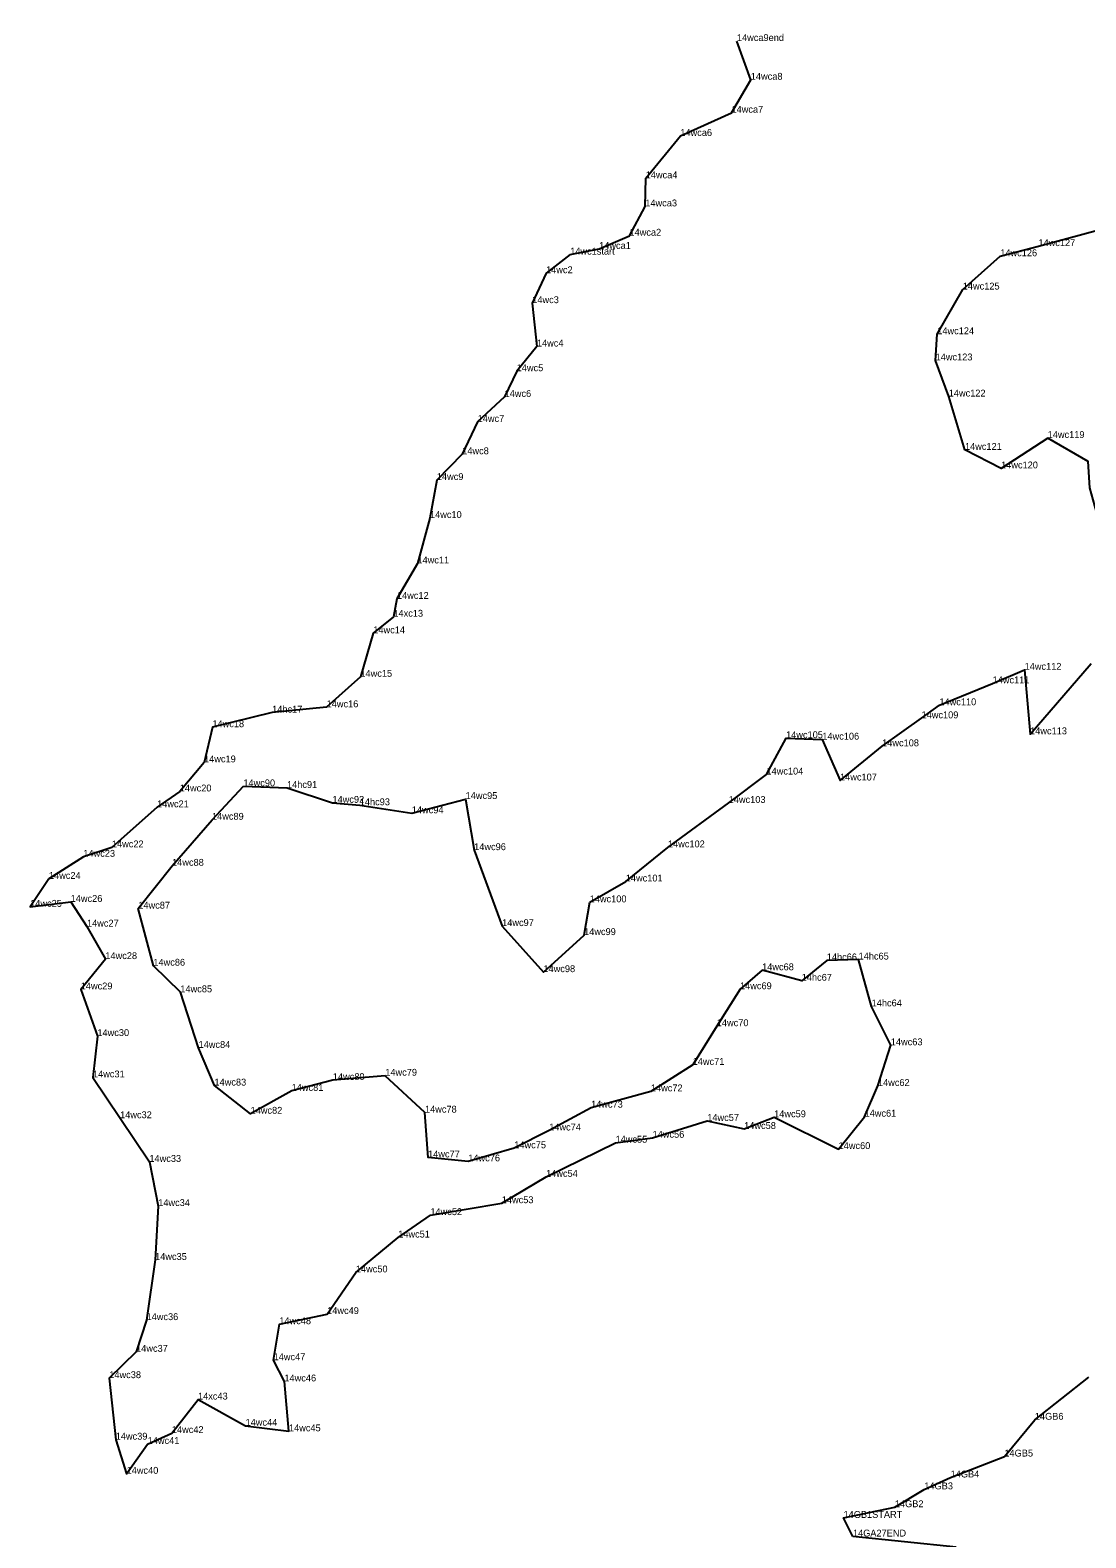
# Model space of a CAD drawing. Extents: x 2072529 to 2267990, y 436423 to 470008.
# Drawn here: x 2255744 to 2256512, y 441770 to 442866 of the extents above; entities that cross this region are included whole.
import ezdxf

# ---------------------------------------------------------------- set-up
doc = ezdxf.new("R2010")
doc.units = 0
doc.layers.add('Level 3', color=7, linetype='Continuous')
doc.layers.add('Old_Level_52', color=7, linetype='Continuous')

msp = doc.modelspace()

# ---------------------------------------------------------------- linework, layer by layer
at = {"layer": 'Level 3'}
for p, q in [((2256257.899, 442858.409), (2256257.899, 442858.409)), ((2256268.003, 442830.249), (2256268.003, 442830.249)), ((2256253.969, 442806.261), (2256253.969, 442806.261)), ((2256216.767, 442789.425), (2256216.767, 442789.425)), ((2256191.599, 442758.624), (2256191.599, 442758.624)), ((2256191.305, 442738.169), (2256191.305, 442738.169)), ((2256179.78, 442716.87), (2256179.78, 442716.87)), ((2256136.696, 442703.1), (2256136.696, 442703.1)), ((2256157.731, 442707.258), (2256157.731, 442707.258)), ((2256449.372, 442701.938), (2256449.372, 442701.938)), ((2256477.101, 442709.298), (2256477.101, 442709.298)), ((2256119.139, 442689.606), (2256119.139, 442689.606)), ((2256422.088, 442677.722), (2256422.088, 442677.722)), ((2256109.115, 442667.828), (2256109.115, 442667.828)), ((2256403.543, 442645.218), (2256403.543, 442645.218)), ((2256112.493, 442636.286), (2256112.493, 442636.286)), ((2256402.361, 442626.184), (2256402.361, 442626.184)), ((2256097.804, 442618.346), (2256097.804, 442618.346)), ((2256088.992, 442599.644), (2256088.992, 442599.644)), ((2256411.887, 442599.94), (2256411.887, 442599.94)), ((2256069.424, 442581.458), (2256069.424, 442581.458)), ((2256483.83, 442569.775), (2256483.83, 442569.775)), ((2256058.196, 442557.949), (2256058.196, 442557.949)), ((2256423.695, 442561.134), (2256423.695, 442561.134)), ((2256449.942, 442547.661), (2256449.942, 442547.661)), ((2256039.742, 442539.213), (2256039.742, 442539.213)), ((2256034.772, 442511.586), (2256034.772, 442511.586)), ((2256025.637, 442478.575), (2256025.637, 442478.575)), ((2256010.763, 442452.788), (2256010.763, 442452.788)), ((2256008.17, 442439.828), (2256008.17, 442439.828)), ((2255993.551, 442427.775), (2255993.551, 442427.775)), ((2255984.174, 442396.146), (2255984.174, 442396.146)), ((2256467.056, 442401.237), (2256467.056, 442401.237)), ((2256443.754, 442391.374), (2256443.754, 442391.374)), ((2255920.019, 442370.069), (2255920.019, 442370.069)), ((2255959.616, 442373.969), (2255959.616, 442373.969)), ((2256405.101, 442375.447), (2256405.101, 442375.447)), ((2255876.591, 442359.51), (2255876.591, 442359.51)), ((2256392.12, 442365.972), (2256392.12, 442365.972)), ((2256293.64, 442351.509), (2256293.64, 442351.509)), ((2256319.992, 442350.448), (2256319.992, 442350.448)), ((2256471.058, 442354.313), (2256471.058, 442354.313)), ((2256363.47, 442345.612), (2256363.47, 442345.612)), ((2255870.51, 442333.901), (2255870.51, 442333.901)), ((2255899.103, 442316.518), (2255899.103, 442316.518)), ((2255930.823, 442315.302), (2255930.823, 442315.302)), ((2256279.387, 442325.079), (2256279.387, 442325.079)), ((2256332.867, 442320.741), (2256332.867, 442320.741)), ((2255852.869, 442312.776), (2255852.869, 442312.776)), ((2255963.868, 442304.513), (2255963.868, 442304.513)), ((2256060.665, 442307.265), (2256060.665, 442307.265)), ((2256251.929, 442304.418), (2256251.929, 442304.418)), ((2255836.387, 442301.236), (2255836.387, 442301.236)), ((2255983.714, 442302.732), (2255983.714, 442302.732)), ((2256021.559, 442296.894), (2256021.559, 442296.894)), ((2255876.303, 442292.187), (2255876.303, 442292.187)), ((2255803.524, 442272.108), (2255803.524, 442272.108)), ((2256207.755, 442272.121), (2256207.755, 442272.121)), ((2255782.767, 442265.278), (2255782.767, 442265.278)), ((2256066.889, 442270.09), (2256066.889, 442270.09)), ((2255847.281, 442258.718), (2255847.281, 442258.718)), ((2255757.754, 442249.211), (2255757.754, 442249.211)), ((2256177.113, 442247.308), (2256177.113, 442247.308)), ((2255744.096, 442228.902), (2255744.096, 442228.902)), ((2255773.544, 442232.484), (2255773.544, 442232.484)), ((2255822.729, 442227.549), (2255822.729, 442227.549)), ((2256150.866, 442232.18), (2256150.866, 442232.18)), ((2255785.395, 442214.491), (2255785.395, 442214.491)), ((2256087.213, 442214.888), (2256087.213, 442214.888)), ((2256146.807, 442208.328), (2256146.807, 442208.328)), ((2255798.772, 442190.873), (2255798.772, 442190.873)), ((2255833.668, 442186.065), (2255833.668, 442186.065)), ((2256323.244, 442189.952), (2256323.244, 442189.952)), ((2256346.351, 442190.546), (2256346.351, 442190.546)), ((2256117.242, 442181.383), (2256117.242, 442181.383)), ((2256276.219, 442182.731), (2256276.219, 442182.731)), ((2256305.007, 442175.125), (2256305.007, 442175.125)), ((2255780.866, 442168.821), (2255780.866, 442168.821)), ((2255853.292, 442166.716), (2255853.292, 442166.716)), ((2256260.148, 442168.971), (2256260.148, 442168.971)), ((2256355.84, 442156.485), (2256355.84, 442156.485)), ((2256243.265, 442142.091), (2256243.265, 442142.091)), ((2255792.976, 442134.911), (2255792.976, 442134.911)), ((2255866.534, 442126.301), (2255866.534, 442126.301)), ((2256369.778, 442128.2), (2256369.778, 442128.2)), ((2256225.739, 442113.955), (2256225.739, 442113.955)), ((2255789.763, 442104.845), (2255789.763, 442104.845)), ((2255878.097, 442098.932), (2255878.097, 442098.932)), ((2255964.148, 442102.908), (2255964.148, 442102.908)), ((2256002.269, 442106.075), (2256002.269, 442106.075)), ((2256360.431, 442098.624), (2256360.431, 442098.624)), ((2255934.208, 442095.058), (2255934.208, 442095.058)), ((2256195.361, 442094.695), (2256195.361, 442094.695)), ((2255809.494, 442075.166), (2255809.494, 442075.166)), ((2255904.34, 442078.415), (2255904.34, 442078.415)), ((2256031.122, 442079.233), (2256031.122, 442079.233)), ((2256151.89, 442082.831), (2256151.89, 442082.831)), ((2256284.96, 442075.849), (2256284.96, 442075.849)), ((2256350.682, 442076.296), (2256350.682, 442076.296)), ((2256121.423, 442066.246), (2256121.423, 442066.246)), ((2256236.354, 442073.185), (2256236.354, 442073.185)), ((2256263.174, 442067.345), (2256263.174, 442067.345)), ((2256096.044, 442053.339), (2256096.044, 442053.339)), ((2256169.669, 442057.394), (2256169.669, 442057.394)), ((2256196.594, 442060.973), (2256196.594, 442060.973)), ((2256331.83, 442052.73), (2256331.83, 442052.73)), ((2255830.779, 442043.437), (2255830.779, 442043.437)), ((2256033.387, 442046.65), (2256033.387, 442046.65)), ((2256062.616, 442043.786), (2256062.616, 442043.786)), ((2256119.15, 442032.539), (2256119.15, 442032.539)), ((2255837.199, 442011.3), (2255837.199, 442011.3)), ((2256086.951, 442013.397), (2256086.951, 442013.397)), ((2256035.058, 442004.729), (2256035.058, 442004.729)), ((2256011.663, 441988.423), (2256011.663, 441988.423)), ((2255834.935, 441972.101), (2255834.935, 441972.101)), ((2255980.875, 441963.057), (2255980.875, 441963.057)), ((2255960.013, 441932.787), (2255960.013, 441932.787)), ((2255828.711, 441928.367), (2255828.711, 441928.367)), ((2255925.244, 441925.413), (2255925.244, 441925.413)), ((2255821.132, 441905.33), (2255821.132, 441905.33)), ((2255921.081, 441899.221), (2255921.081, 441899.221)), ((2255801.631, 441886.172), (2255801.631, 441886.172)), ((2255928.939, 441883.778), (2255928.939, 441883.778)), ((2255866.135, 441870.601), (2255866.135, 441870.601)), ((2256474.479, 441855.925), (2256474.479, 441855.925)), ((2255847.112, 441846.241), (2255847.112, 441846.241)), ((2255900.699, 441851.57), (2255900.699, 441851.57)), ((2255932.24, 441847.51), (2255932.24, 441847.51)), ((2255806.291, 441841.436), (2255806.291, 441841.436)), ((2255829.504, 441838.277), (2255829.504, 441838.277)), ((2256452.361, 441829.174), (2256452.361, 441829.174)), ((2255814.235, 441816.63), (2255814.235, 441816.63)), ((2256413.276, 441813.96), (2256413.276, 441813.96)), ((2256394.141, 441805.326), (2256394.141, 441805.326)), ((2256372.727, 441792.326), (2256372.727, 441792.326)), ((2256335.397, 441784.546), (2256335.397, 441784.546)), ((2256342.251, 441771.007), (2256342.251, 441771.007))]:
    msp.add_line(p, q, dxfattribs=at)
at = {"layer": 'Old_Level_52'}
for points in [[(2256524.048, 442498.667), (2256514.351, 442533.633), (2256513.243, 442552.763), (2256483.83, 442569.775), (2256449.942, 442547.661), (2256423.695, 442561.134), (2256411.887, 442599.94), (2256402.361, 442626.184), (2256403.543, 442645.218), (2256422.088, 442677.722), (2256449.372, 442701.938), (2256477.101, 442709.298), (2256521.047, 442721.188), (2256546.961, 442756.391), (2256554.839, 442794.87), (2256588.861, 442866.33)], [(2256136.696, 442703.1), (2256157.731, 442707.258), (2256179.78, 442716.87), (2256191.305, 442738.169), (2256191.599, 442758.624), (2256216.767, 442789.425), (2256253.969, 442806.261), (2256268.003, 442830.249), (2256257.899, 442858.409)], [(2256136.696, 442703.1), (2256119.139, 442689.606), (2256109.115, 442667.828), (2256112.493, 442636.286), (2256097.804, 442618.346), (2256088.992, 442599.644), (2256069.424, 442581.458), (2256058.196, 442557.949), (2256039.742, 442539.213), (2256034.772, 442511.586), (2256025.637, 442478.575), (2256010.763, 442452.788), (2256008.17, 442439.828), (2255993.551, 442427.775), (2255984.174, 442396.146), (2255959.616, 442373.969), (2255920.019, 442370.069), (2255876.591, 442359.51), (2255870.51, 442333.901), (2255852.869, 442312.776), (2255836.387, 442301.236), (2255803.524, 442272.108), (2255782.767, 442265.278), (2255757.754, 442249.211), (2255744.096, 442228.902), (2255773.544, 442232.484), (2255785.395, 442214.491), (2255798.772, 442190.873), (2255780.866, 442168.821), (2255792.976, 442134.911), (2255789.763, 442104.845), (2255809.494, 442075.166), (2255830.779, 442043.437), (2255837.199, 442011.3), (2255834.935, 441972.101), (2255828.711, 441928.367), (2255821.132, 441905.33), (2255801.631, 441886.172), (2255806.291, 441841.436), (2255814.235, 441816.63), (2255829.504, 441838.277), (2255847.112, 441846.241), (2255866.135, 441870.601), (2255900.699, 441851.57), (2255932.24, 441847.51), (2255928.939, 441883.778), (2255921.081, 441899.221), (2255925.244, 441925.413), (2255960.013, 441932.787), (2255980.875, 441963.057), (2256011.663, 441988.423), (2256035.058, 442004.729), (2256086.951, 442013.397), (2256119.15, 442032.539), (2256169.669, 442057.394), (2256196.594, 442060.973), (2256236.354, 442073.185), (2256263.174, 442067.345), (2256284.96, 442075.849), (2256331.83, 442052.73), (2256350.682, 442076.296), (2256360.431, 442098.624), (2256369.778, 442128.2), (2256355.84, 442156.485), (2256346.351, 442190.546), (2256323.244, 442189.952), (2256305.007, 442175.125), (2256276.219, 442182.731), (2256260.148, 442168.971), (2256243.265, 442142.091), (2256225.739, 442113.955), (2256195.361, 442094.695), (2256151.89, 442082.831), (2256121.423, 442066.246), (2256096.044, 442053.339), (2256062.616, 442043.786), (2256033.387, 442046.65), (2256031.122, 442079.233), (2256002.269, 442106.075), (2255964.148, 442102.908), (2255934.208, 442095.058), (2255904.34, 442078.415), (2255878.097, 442098.932), (2255866.534, 442126.301), (2255853.292, 442166.716), (2255833.668, 442186.065), (2255822.729, 442227.549), (2255847.281, 442258.718), (2255876.303, 442292.187), (2255899.103, 442316.518)], [(2255899.103, 442316.518), (2255930.823, 442315.302), (2255963.868, 442304.513), (2255983.714, 442302.732), (2256021.559, 442296.894), (2256060.665, 442307.265), (2256066.889, 442270.09), (2256087.213, 442214.888), (2256117.242, 442181.383), (2256146.807, 442208.328), (2256150.866, 442232.18), (2256177.113, 442247.308), (2256207.755, 442272.121), (2256251.929, 442304.418), (2256279.387, 442325.079), (2256293.64, 442351.509), (2256319.992, 442350.448), (2256332.867, 442320.741), (2256363.47, 442345.612), (2256392.12, 442365.972), (2256405.101, 442375.447), (2256443.754, 442391.374), (2256467.056, 442401.237), (2256471.058, 442354.313), (2256515.322, 442405.862)], [(2256342.251, 441771.007), (2256335.397, 441784.546), (2256372.727, 441792.326), (2256394.141, 441805.326), (2256413.276, 441813.96), (2256452.361, 441829.174), (2256474.479, 441855.925), (2256513.79, 441886.845)], [(2256417.282, 441763.183), (2256342.251, 441771.007)]]:
    msp.add_lwpolyline(points, dxfattribs=at)

# ---------------------------------------------------------------- texts
for s, p in [('14wca9end', (2256257.899, 442858.409)), ('14wca8', (2256268.003, 442830.249)), ('14wca7', (2256253.969, 442806.261)), ('14wca6', (2256216.767, 442789.425)), ('14wca4', (2256191.599, 442758.624)), ('14wca3', (2256191.305, 442738.169)), ('14wca2', (2256179.78, 442716.87)), ('14wca1', (2256157.731, 442707.258)), ('14wc127', (2256477.101, 442709.298)), ('14wc1start', (2256136.696, 442703.1)), ('14wc126', (2256449.372, 442701.938)), ('14wc2', (2256119.139, 442689.606)), ('14wc125', (2256422.088, 442677.722)), ('14wc3', (2256109.115, 442667.828)), ('14wc124', (2256403.543, 442645.218)), ('14wc4', (2256112.493, 442636.286)), ('14wc5', (2256097.804, 442618.346)), ('14wc123', (2256402.361, 442626.184)), ('14wc6', (2256088.992, 442599.644)), ('14wc122', (2256411.887, 442599.94)), ('14wc7', (2256069.424, 442581.458)), ('14wc119', (2256483.83, 442569.775)), ('14wc8', (2256058.196, 442557.949)), ('14wc121', (2256423.695, 442561.134)), ('14wc120', (2256449.942, 442547.661)), ('14wc9', (2256039.742, 442539.213)), ('14wc10', (2256034.772, 442511.586)), ('14wc11', (2256025.637, 442478.575)), ('14wc12', (2256010.763, 442452.788)), ('14xc13', (2256008.17, 442439.828)), ('14wc14', (2255993.551, 442427.775)), ('14wc112', (2256467.056, 442401.237)), ('14wc15', (2255984.174, 442396.146)), ('14wc111', (2256443.754, 442391.374)), ('14hc17', (2255920.019, 442370.069)), ('14wc16', (2255959.616, 442373.969)), ('14wc109', (2256392.12, 442365.972)), ('14wc110', (2256405.101, 442375.447)), ('14wc18', (2255876.591, 442359.51)), ('14wc113', (2256471.058, 442354.313)), ('14wc105', (2256293.64, 442351.509)), ('14wc106', (2256319.992, 442350.448)), ('14wc108', (2256363.47, 442345.612)), ('14wc19', (2255870.51, 442333.901)), ('14wc104', (2256279.387, 442325.079)), ('14wc20', (2255852.869, 442312.776)), ('14wc90', (2255899.103, 442316.518)), ('14hc91', (2255930.823, 442315.302)), ('14wc107', (2256332.867, 442320.741)), ('14wc21', (2255836.387, 442301.236)), ('14wc92', (2255963.868, 442304.513)), ('14hc93', (2255983.714, 442302.732)), ('14wc95', (2256060.665, 442307.265)), ('14wc103', (2256251.929, 442304.418)), ('14wc89', (2255876.303, 442292.187)), ('14wc94', (2256021.559, 442296.894)), ('14wc22', (2255803.524, 442272.108)), ('14wc96', (2256066.889, 442270.09)), ('14wc102', (2256207.755, 442272.121)), ('14wc23', (2255782.767, 442265.278)), ('14wc88', (2255847.281, 442258.718)), ('14wc24', (2255757.754, 442249.211)), ('14wc101', (2256177.113, 442247.308)), ('14wc25', (2255744.096, 442228.902)), ('14wc26', (2255773.544, 442232.484)), ('14wc87', (2255822.729, 442227.549)), ('14wc100', (2256150.866, 442232.18)), ('14wc27', (2255785.395, 442214.491)), ('14wc97', (2256087.213, 442214.888)), ('14wc99', (2256146.807, 442208.328)), ('14wc28', (2255798.772, 442190.873)), ('14hc66', (2256323.244, 442189.952)), ('14hc65', (2256346.351, 442190.546)), ('14wc86', (2255833.668, 442186.065)), ('14wc98', (2256117.242, 442181.383)), ('14wc68', (2256276.219, 442182.731)), ('14wc29', (2255780.866, 442168.821)), ('14wc69', (2256260.148, 442168.971)), ('14hc67', (2256305.007, 442175.125)), ('14wc85', (2255853.292, 442166.716)), ('14hc64', (2256355.84, 442156.485)), ('14wc30', (2255792.976, 442134.911)), ('14wc70', (2256243.265, 442142.091)), ('14wc84', (2255866.534, 442126.301)), ('14wc63', (2256369.778, 442128.2)), ('14wc71', (2256225.739, 442113.955)), ('14wc31', (2255789.763, 442104.845)), ('14wc80', (2255964.148, 442102.908)), ('14wc79', (2256002.269, 442106.075)), ('14wc83', (2255878.097, 442098.932)), ('14wc81', (2255934.208, 442095.058)), ('14wc72', (2256195.361, 442094.695)), ('14wc62', (2256360.431, 442098.624)), ('14wc73', (2256151.89, 442082.831)), ('14wc32', (2255809.494, 442075.166)), ('14wc82', (2255904.34, 442078.415)), ('14wc78', (2256031.122, 442079.233)), ('14wc57', (2256236.354, 442073.185)), ('14wc59', (2256284.96, 442075.849)), ('14wc61', (2256350.682, 442076.296)), ('14wc74', (2256121.423, 442066.246)), ('14wc56', (2256196.594, 442060.973)), ('14wc58', (2256263.174, 442067.345)), ('14wc75', (2256096.044, 442053.339)), ('14wc55', (2256169.669, 442057.394)), ('14wc60', (2256331.83, 442052.73)), ('14wc33', (2255830.779, 442043.437)), ('14wc77', (2256033.387, 442046.65)), ('14wc76', (2256062.616, 442043.786)), ('14wc54', (2256119.15, 442032.539)), ('14wc34', (2255837.199, 442011.3)), ('14wc52', (2256035.058, 442004.729)), ('14wc53', (2256086.951, 442013.397)), ('14wc51', (2256011.663, 441988.423)), ('14wc35', (2255834.935, 441972.101)), ('14wc50', (2255980.875, 441963.057)), ('14wc36', (2255828.711, 441928.367)), ('14wc49', (2255960.013, 441932.787)), ('14wc48', (2255925.244, 441925.413)), ('14wc37', (2255821.132, 441905.33)), ('14wc47', (2255921.081, 441899.221)), ('14wc38', (2255801.631, 441886.172)), ('14wc46', (2255928.939, 441883.778)), ('14xc43', (2255866.135, 441870.601)), ('14wc44', (2255900.699, 441851.57)), ('14GB6', (2256474.479, 441855.925)), ('14wc39', (2255806.291, 441841.436)), ('14wc42', (2255847.112, 441846.241)), ('14wc45', (2255932.24, 441847.51)), ('14wc41', (2255829.504, 441838.277)), ('14GB5', (2256452.361, 441829.174)), ('14wc40', (2255814.235, 441816.63)), ('14GB4', (2256413.276, 441813.96)), ('14GB3', (2256394.141, 441805.326)), ('14GB1START', (2256335.397, 441784.546)), ('14GB2', (2256372.727, 441792.326)), ('14GA27END', (2256342.251, 441771.007))]:
    msp.add_text(s, height=5).set_placement(p)

doc.saveas('drawing.dxf')
